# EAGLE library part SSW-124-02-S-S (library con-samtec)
THROUGH-HOLE .025" SQ POST SOCKET Source: Samtec SSW.pdf
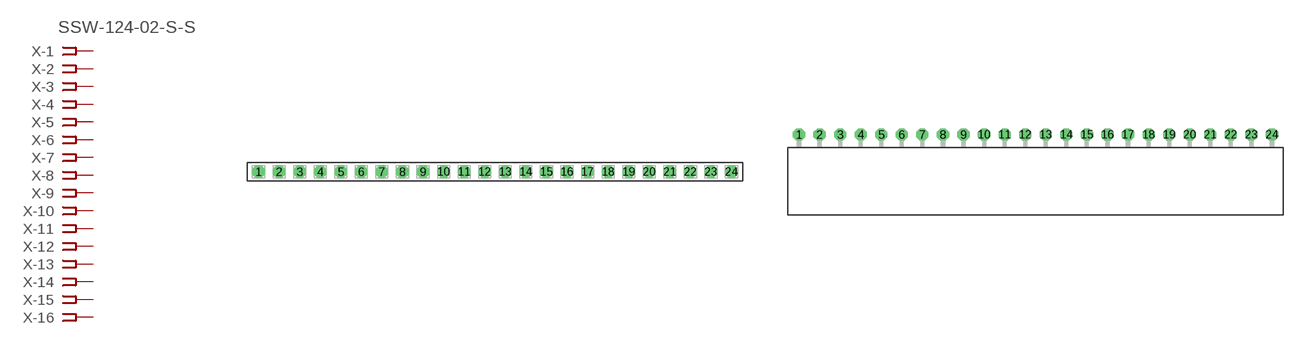
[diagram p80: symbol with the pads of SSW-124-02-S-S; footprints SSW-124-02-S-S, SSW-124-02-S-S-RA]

Designator prefix X; gates -1=FPINV -2=FPIN -3=FPIN -4=FPIN -5=FPIN -6=FPIN -7=FPIN -8=FPIN -9=FPIN -10=FPIN -11=FPIN -12=FPIN -13=FPIN -14=FPIN -15=FPIN -16=FPIN -17=FPIN -18=FPIN -19=FPIN -20=FPIN -21=FPIN -22=FPIN -23=FPIN -24=FPIN

## SSW-124-02-S-S (MPN: SSW-124-02-S-S; OC_FARNELL: unknown; OC_NEWARK: 11P9709)  [SSW-124-02-S-S]
1  -1:1  pas
2  -2:1  pas
3  -3:1  pas
4  -4:1  pas
5  -5:1  pas
6  -6:1  pas
7  -7:1  pas
8  -8:1  pas
9  -9:1  pas
10  -10:1  pas
11  -11:1  pas
12  -12:1  pas
13  -13:1  pas
14  -14:1  pas
15  -15:1  pas
16  -16:1  pas
17  -17:1  pas
18  -18:1  pas
19  -19:1  pas
20  -20:1  pas
21  -21:1  pas
22  -22:1  pas
23  -23:1  pas
24  -24:1  pas

## SSW-124-02-S-S-RA (MPN: SSW-124-02-S-S-RA; OC_FARNELL: unknown; OC_NEWARK: 11P9710)  [SSW-124-02-S-S-RA]
Pads as for SSW-124-02-S-S

## Footprint SSW-124-02-S-S (pad centres in mm)
THROUGH-HOLE .025" SQ POST SOCKET Source: Samtec SSW.pdf
drill 1 pad 1.5 octagon: 1 -29.21,0; 2 -26.67,0; 3 -24.13,0; 4 -21.59,0; 5 -19.05,0; 6 -16.51,0; 7 -13.97,0; 8 -11.43,0; 9 -8.89,0; 10 -6.35,0; 11 -3.81,0; 12 -1.27,0; 13 1.27,0; 14 3.81,0; 15 6.35,0; 16 8.89,0; 17 11.43,0; 18 13.97,0; 19 16.51,0; 20 19.05,0; 21 21.59,0; 22 24.13,0; 23 26.67,0; 24 29.21,0

## Footprint SSW-124-02-S-S-RA (pad centres in mm)
THROUGH-HOLE .025" SQ POST SOCKET Source: Samtec SSW.pdf
drill 1 pad 1.5 octagon: 1 -29.21,1.524; 2 -26.67,1.524; 3 -24.13,1.524; 4 -21.59,1.524; 5 -19.05,1.524; 6 -16.51,1.524; 7 -13.97,1.524; 8 -11.43,1.524; 9 -8.89,1.524; 10 -6.35,1.524; 11 -3.81,1.524; 12 -1.27,1.524; 13 1.27,1.524; 14 3.81,1.524; 15 6.35,1.524; 16 8.89,1.524; 17 11.43,1.524; 18 13.97,1.524; 19 16.51,1.524; 20 19.05,1.524; 21 21.59,1.524; 22 24.13,1.524; 23 26.67,1.524; 24 29.21,1.524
